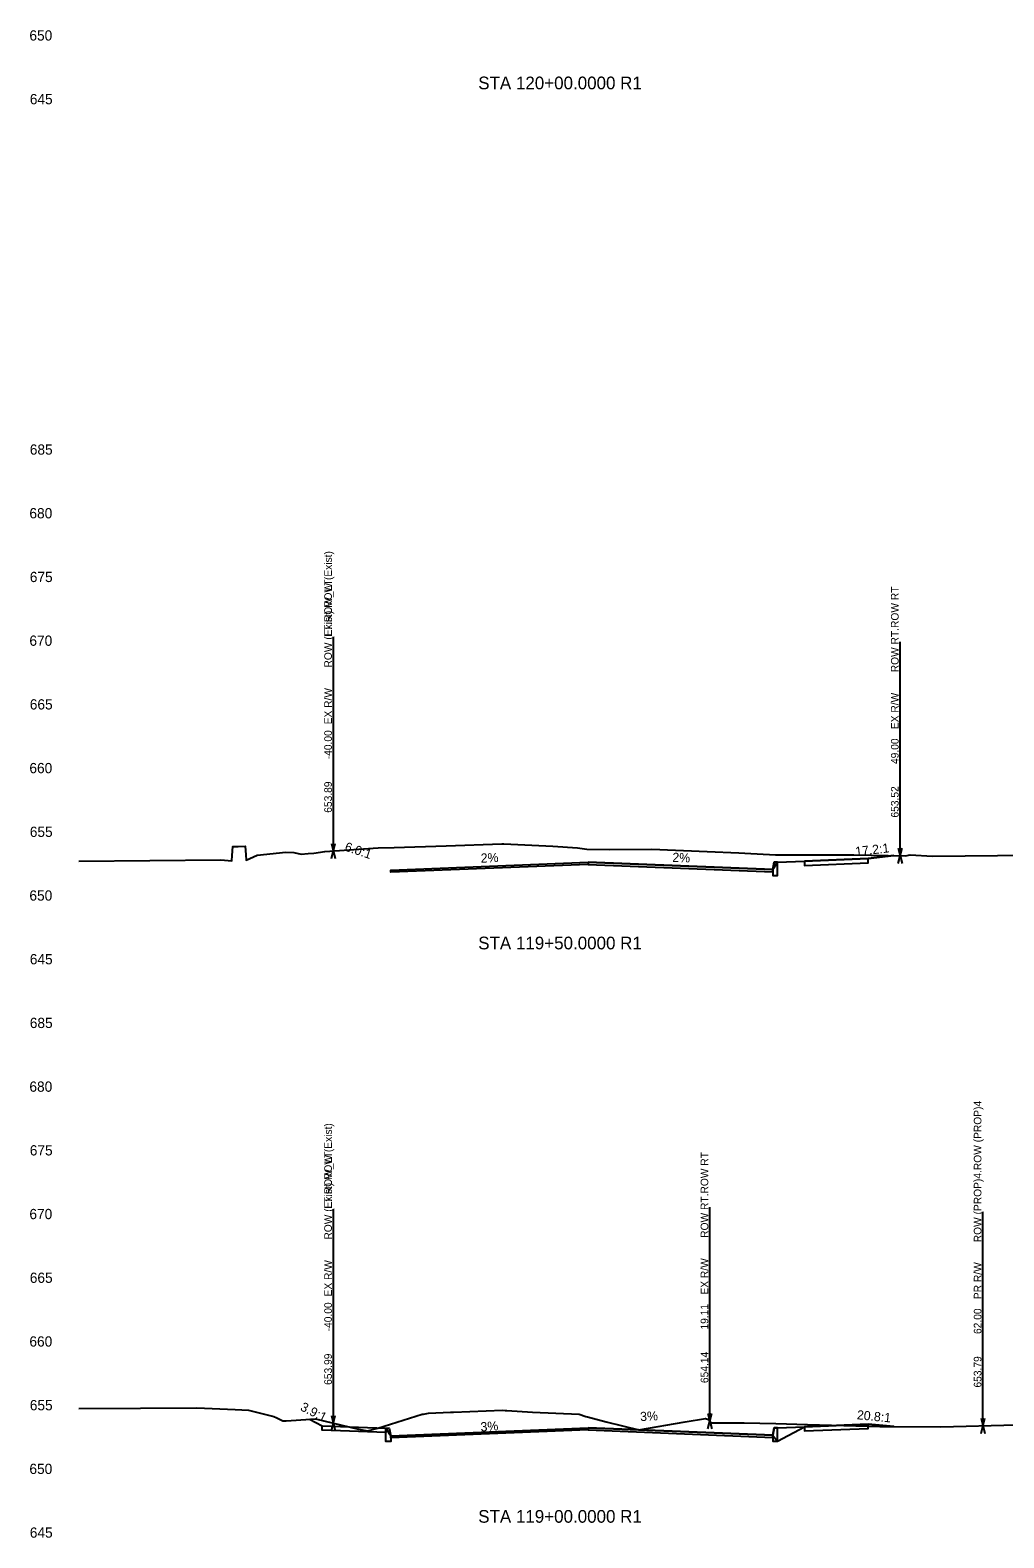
# Model space of a CAD drawing. Extents: x 2 to 741, y 16 to 2207.
# Drawn here: x 2.4 to 155.3, y 30 to 266.6 of the extents above; entities that cross this region are included whole.
import ezdxf

# ---------------------------------------------------------------- set-up
doc = ezdxf.new("R2010")
doc.units = 0
for name, color, linetype in [('Draft_XS_Feature_Name', 7, 'Continuous'), ('Draft_XS_Label', 7, 'Continuous'), ('Draft_XS_Point_Label_Indicator', 7, 'Continuous'), ('Draft_XS_Terminator', 7, 'Continuous'), ('Draft_XS_Text', 7, 'Continuous'), ('E_ROW', 7, 'Continuous'), ('E_Terrain_Exterior', 7, 'Continuous'), ('E_Terrain_Points_Low', 7, 'Continuous'), ('Grade_Veg_Grass', 7, 'Continuous'), ('P_XS_Sections', 7, 'Continuous'), ('PROP_ROW', 7, 'Continuous'), ('Road_Curb', 7, 'Continuous'), ('Road_Pave_Asphalt', 7, 'Continuous'), ('Road_Sidewalk', 7, 'Continuous'), ('Terrain_Design', 7, 'Continuous')]:
    doc.layers.add(name, color=color, linetype=linetype)

msp = doc.modelspace()

# ---------------------------------------------------------------- linework, layer by layer
at = {"layer": 'Draft_XS_Terminator'}
for p, q in [((50, 137.79), (50, 159.79)), ((50, 137.79), (50, 159.79)), ((139, 137.04), (139, 159.04)), ((50, 47.99), (50, 69.99)), ((50, 47.99), (50, 69.99)), ((109.11, 48.27), (109.11, 70.27)), ((152, 47.57), (152, 69.57))]:
    msp.add_line(p, q, dxfattribs=at)
at = {"layer": 'E_ROW'}
for p, q in [((50, 137.79), (50, 171.39)), ((50, 137.79), (50, 171.39)), ((139, 137.04), (139, 170.64)), ((49.7, 136.59), (50.3, 138.99)), ((49.7, 138.99), (50.3, 136.59)), ((49.7, 136.59), (50.3, 138.99)), ((49.7, 138.99), (50.3, 136.59)), ((138.7, 135.84), (139.3, 138.24)), ((138.7, 138.24), (139.3, 135.84)), ((50, 47.99), (50, 81.59)), ((50, 47.99), (50, 81.59)), ((109.11, 48.27), (109.11, 81.87)), ((49.7, 46.79), (50.3, 49.19)), ((49.7, 49.19), (50.3, 46.79)), ((49.7, 46.79), (50.3, 49.19)), ((49.7, 49.19), (50.3, 46.79)), ((108.81, 47.07), (109.41, 49.47)), ((108.81, 49.47), (109.41, 47.07))]:
    msp.add_line(p, q, dxfattribs=at)
at = {"layer": 'E_Terrain_Exterior'}
for points in [[(10, 136.17), (32.34, 136.38), (34.07, 136.26), (34.12, 137.09), (34.19, 138.49), (35.02, 138.51), (36.12, 138.55), (36.23, 137.18), (36.29, 136.37), (38.02, 137.14), (42.54, 137.62), (43.78, 137.53), (44.95, 137.27), (46.05, 137.38), (46.91, 137.47), (48.65, 137.69), (57.03, 138.29), (59.53, 138.35), (67.69, 138.62), (76.44, 138.93), (76.74, 138.92), (84.43, 138.55), (88.31, 138.29), (89.82, 138.07), (93.33, 138), (100.01, 138.09), (108.69, 137.72), (113.68, 137.49), (114.59, 137.43), (119.41, 137.19), (131.73, 137.19), (139.83, 137.02), (140.58, 137.17), (144.07, 136.99), (159.39, 137.11)], [(10, 50.27), (19.71, 50.35), (28.53, 50.4), (34.55, 50.1), (36.68, 50), (40.66, 49.02), (41.11, 48.84), (42.08, 48.37), (42.57, 48.32), (43.34, 48.4), (47.16, 48.65), (53.96, 47.06), (55.35, 46.77), (56.96, 47.18), (63.96, 49.37), (64.12, 49.4), (64.93, 49.55), (68.36, 49.7), (68.88, 49.71), (76.57, 50), (76.99, 49.98), (77.21, 49.98), (81.24, 49.73), (88.59, 49.39), (89.64, 49.03), (89.88, 48.96), (92.82, 48.2), (97.95, 46.94), (105.22, 48.21), (108.44, 48.71), (108.77, 48.63), (108.77, 48.63), (108.81, 48.59), (108.81, 48.59), (108.81, 48.58), (108.87, 48.53), (108.93, 48.46), (108.94, 48.45), (108.94, 48.45), (109.05, 48.34), (109.21, 48.17), (109.22, 48.16), (109.23, 48.15), (109.35, 48.02), (114.37, 48.04), (114.49, 48.04), (116.98, 48), (119.49, 47.92), (124.46, 47.78), (135.83, 47.44), (145.41, 47.41), (157.29, 47.71)]]:
    msp.add_lwpolyline(points, dxfattribs=at)
at = {"layer": 'Grade_Veg_Grass'}
for points in [[(119.75, 136.03), (124, 136.2)], [(138, 137.06), (134, 136.6), (134, 136.6)], [(46.25, 48.59), (48.25, 47.57), (48.25, 47.57)], [(119.75, 47.25), (124, 47.42)], [(138, 47.43), (138, 47.43), (134, 47.82)]]:
    msp.add_lwpolyline(points, dxfattribs=at)
at = {"layer": 'PROP_ROW'}
for p, q in [((152, 47.57), (152, 81.17)), ((151.7, 46.37), (152.3, 48.77)), ((151.7, 48.77), (152.3, 46.37))]:
    msp.add_line(p, q, dxfattribs=at)
at = {"layer": 'Road_Curb'}
for points in [[(119, 134.86), (119, 133.94), (119.75, 133.94), (119.75, 136.03), (119.23, 136.03), (119, 134.86)], [(59, 46), (59, 45.08), (58.25, 45.08), (58.25, 47.17), (58.77, 47.17), (59, 46)], [(119, 46.08), (119, 45.16), (119.75, 45.16), (119.75, 47.25), (119.23, 47.25), (119, 46.08)]]:
    msp.add_lwpolyline(points, dxfattribs=at)
at = {"layer": 'Road_Pave_Asphalt'}
for points in [[(90, 136.02), (90, 135.69), (59, 134.45), (59, 134.78), (90, 136.02)], [(90, 136.02), (90, 135.69), (119, 134.53), (119, 134.86), (90, 136.02)], [(90, 47.24), (90, 46.91), (59, 45.67), (59, 46), (90, 47.24)], [(90, 47.24), (90, 46.91), (119, 45.75), (119, 46.08), (90, 47.24)]]:
    msp.add_lwpolyline(points, dxfattribs=at)
at = {"layer": 'Road_Sidewalk'}
for points in [[(124, 136.2), (124, 135.53), (134, 135.93), (134, 136.6), (124, 136.2)], [(58.25, 47.17), (58.25, 46.5), (48.25, 46.9), (48.25, 47.57), (58.25, 47.17)], [(124, 47.42), (124, 46.75), (134, 47.15), (134, 47.82), (124, 47.42)]]:
    msp.add_lwpolyline(points, dxfattribs=at)
at = {"layer": 'Terrain_Design'}
for points in [[(59, 134.78), (90, 136.02), (119, 134.86), (119.23, 136.03), (119.75, 136.03), (124, 136.2), (134, 136.6), (138, 137.06)], [(59, 134.78), (90, 136.02), (119, 134.86), (119.23, 135.22), (119.75, 136.03), (124, 136.2), (134, 136.6), (138, 137.06)], [(46.25, 48.59), (48.25, 47.57), (58.25, 47.17), (58.77, 47.17), (59, 46), (90, 47.24), (119, 46.08), (119.23, 47.25), (119.75, 47.25), (124, 47.42), (134, 47.82), (138, 47.43), (138, 47.43)], [(46.25, 48.59), (48.25, 47.57), (58.25, 47.17), (58.77, 46.36), (59, 46), (90, 47.24), (119, 46.08), (119.23, 45.8), (119.75, 45.16), (124, 47.42), (134, 47.82), (138, 47.43), (138, 47.43)]]:
    msp.add_lwpolyline(points, dxfattribs=at)

# ---------------------------------------------------------------- texts
at = {"layer": 'Draft_XS_Feature_Name'}
for s, p in [('ROW (Exist).ROW (Exist)', (49.76, 166.59)), ('ROW_LT.ROW_LT', (49.76, 166.59)), ('ROW RT.ROW RT', (138.76, 165.84)), ('ROW (PROP)4.ROW (PROP)4', (151.76, 76.37)), ('ROW (Exist).ROW (Exist)', (49.76, 76.79)), ('ROW_LT.ROW_LT', (49.76, 76.79)), ('ROW RT.ROW RT', (108.87, 77.07))]:
    msp.add_text(s, height=1.2, rotation=90, dxfattribs=at).set_placement(p)
at = {"layer": 'Draft_XS_Label'}
for s, p in [('-40.00', (49.76, 152.19)), ('-40.00', (49.76, 152.19)), ('49.00', (138.76, 151.44)), ('653.89', (49.76, 143.79)), ('653.89', (49.76, 143.79)), ('653.52', (138.76, 143.04)), ('-40.00', (49.76, 62.39)), ('-40.00', (49.76, 62.39)), ('19.11', (108.87, 62.67)), ('62.00', (151.76, 61.97)), ('653.99', (49.76, 53.99)), ('653.99', (49.76, 53.99)), ('654.14', (108.87, 54.27)), ('653.79', (151.76, 53.57))]:
    msp.add_text(s, height=1.2, rotation=90, dxfattribs=at).set_placement(p)
at = {"layer": 'Draft_XS_Point_Label_Indicator'}
for p in [(119.22, 136.02), (119.74, 136.02), (123.99, 136.19), (133.99, 136.59), (137.99, 137.05), (58.99, 134.77), (118.99, 134.85), (118.99, 133.93), (46.24, 48.58), (48.24, 47.56), (123.99, 47.41), (133.99, 47.81), (137.99, 47.42), (58.24, 47.16), (58.76, 47.16), (58.99, 45.99), (58.99, 45.07), (118.99, 46.07), (118.99, 45.15), (119.22, 47.24), (119.74, 47.24)]:
    msp.add_text('X', height=0.024, dxfattribs=at).set_placement(p)
at = {"layer": 'Draft_XS_Text'}
for s, height, p in [('650', 1.608, (2.26, 265)), ('STA 120+00.0000 R1', 1.992, (72.74, 257.35)), ('645', 1.608, (2.32, 255)), ('685', 1.608, (2.32, 200)), ('680', 1.608, (2.26, 190)), ('675', 1.608, (2.32, 180)), ('670', 1.608, (2.26, 170)), ('665', 1.608, (2.32, 160)), ('660', 1.608, (2.26, 150)), ('655', 1.608, (2.32, 140)), ('650', 1.608, (2.26, 130)), ('STA 119+50.0000 R1', 1.992, (72.74, 122.35)), ('645', 1.608, (2.32, 120)), ('685', 1.608, (2.32, 110)), ('680', 1.608, (2.26, 100)), ('675', 1.608, (2.32, 90)), ('670', 1.608, (2.26, 80)), ('665', 1.608, (2.32, 70)), ('660', 1.608, (2.26, 60)), ('655', 1.608, (2.32, 50)), ('650', 1.608, (2.26, 40)), ('STA 119+00.0000 R1', 1.992, (72.74, 32.35)), ('645', 1.608, (2.32, 30))]:
    msp.add_text(s, height=height, dxfattribs=at).set_placement(p)
for s, rotation, p in [('6.0:1', 341.5163, (51.66, 137.87)), ('2%', 2.2906, (73.16, 135.95)), ('2%', 357.7094, (103.21, 136.09)), ('17.2:1', 6.6315, (132.04, 136.97)), ('3.9:1', 332.8879, (44.68, 50.07)), ('3%', 3.0939, (98.21, 48.29)), ('20.8:1', 354.5131, (132.16, 48.6)), ('3%', 3.9796, (73.15, 46.67))]:
    msp.add_text(s, height=1.44, rotation=rotation, dxfattribs=at).set_placement(p)
at = {"layer": 'E_ROW'}
for p in [(49.76, 157.67), (49.76, 157.67), (138.76, 156.92), (49.76, 67.87), (49.76, 67.87), (108.87, 68.16)]:
    msp.add_text('EX R/W', height=1.2, rotation=90, dxfattribs=at).set_placement(p)
at = {"layer": 'E_Terrain_Points_Low'}
for p in [(89.99, 136.01), (89.99, 47.23)]:
    msp.add_text('X', height=0.024, dxfattribs=at).set_placement(p)
at = {"layer": 'P_XS_Sections'}
for p in [(10, 255), (10, 120), (10, 30)]:
    msp.add_text('-', height=0.0001, dxfattribs=at).set_placement(p)
at = {"layer": 'PROP_ROW'}
msp.add_text('PR R/W', height=1.2, rotation=90, dxfattribs=at).set_placement((151.76, 67.45))

doc.saveas('drawing.dxf')
